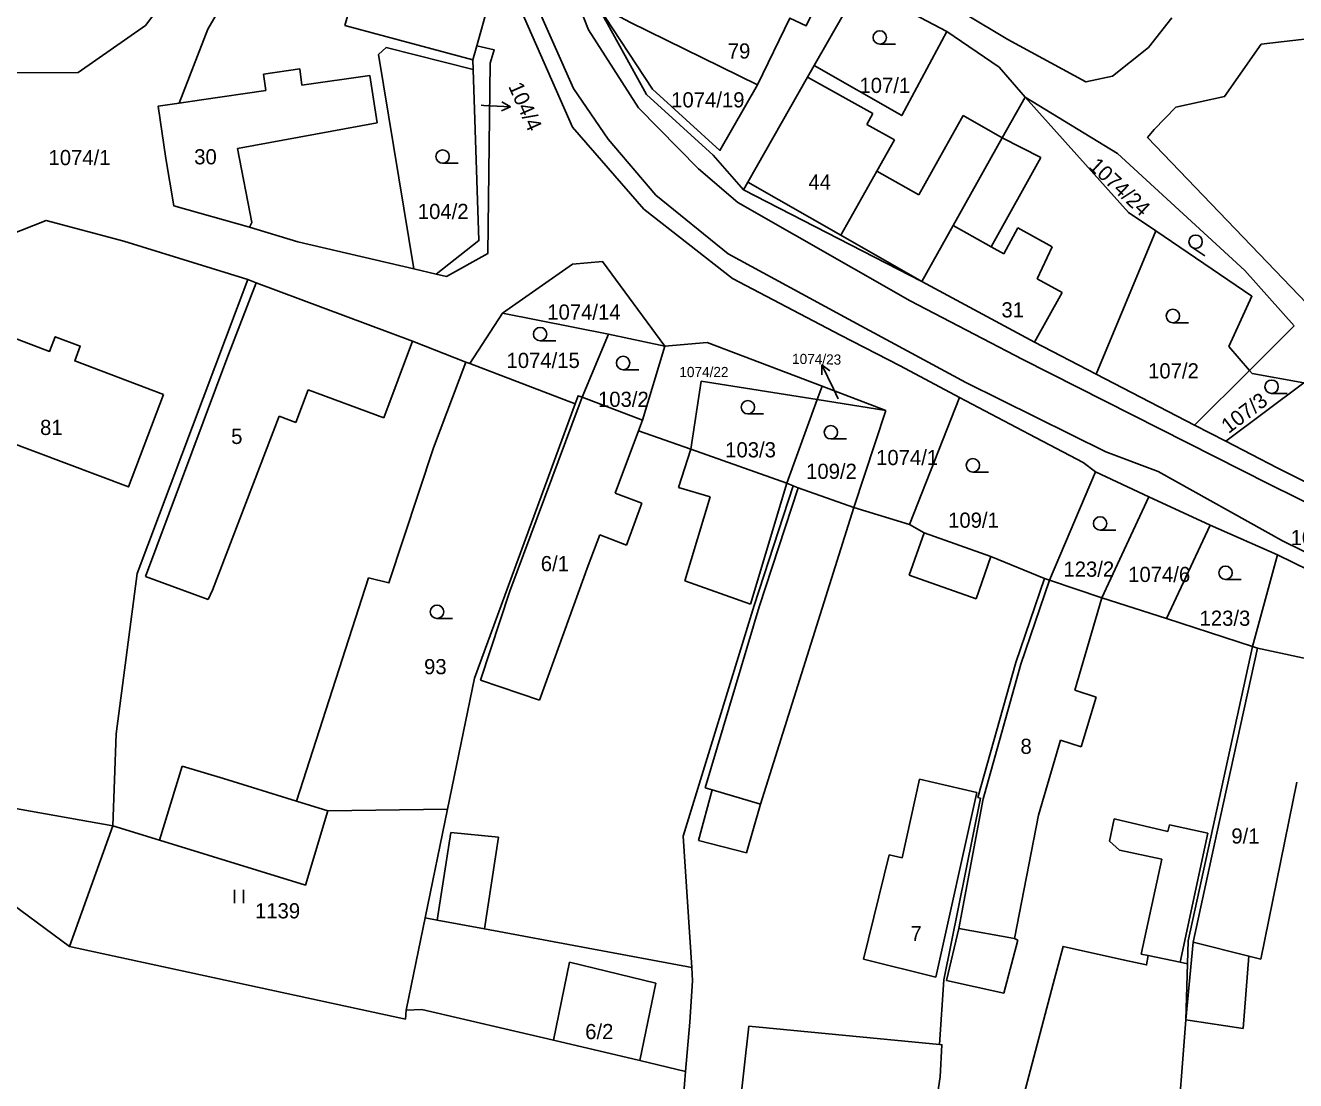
# Model space of a CAD drawing. Extents: x -746176 to -739709, y -1127410 to -1124482.
# Drawn here: x -742376.1 to -742233.7, y -1126206.3 to -1126088.1 of the extents above; entities that cross this region are included whole.
import ezdxf

# ---------------------------------------------------------------- set-up
doc = ezdxf.new("R2010")
doc.units = 0
for name, color, linetype in [('Hranice parcel', 7, 'Continuous'), ('Parcelní čísla', 7, 'Continuous'), ('Pop  PČ popisy', 7, 'Continuous'), ('Vnitřní kresba', 7, 'Continuous'), ('Značky kultur', 7, 'Continuous')]:
    doc.layers.add(name, color=color, linetype=linetype)

msp = doc.modelspace()

# ---------------------------------------------------------------- linework, layer by layer
at = {"layer": 'Hranice parcel'}
for p, q in [((-742325.49, -1126090.34), (-742323.96, -1126084.83)), ((-742325.49, -1126090.34), (-742325.92, -1126091.9)), ((-742325.92, -1126091.9), (-742325.89, -1126092.98)), ((-742263.99, -1126096.11), (-742253.64, -1126102.41)), ((-742275.57, -1126116.75), (-742295.57, -1126106.49)), ((-742256.06, -1126127.14), (-742249.36, -1126111.09)), ((-742332.55, -1126115.34), (-742330.04, -1126115.93)), ((-742326.25, -1126125.97), (-742322.59, -1126120.3)), ((-742322.59, -1126120.3), (-742310.73, -1126122.68)), ((-742233.84, -1126121.75), (-742238.85, -1126126.73)), ((-742310.73, -1126122.68), (-742313.65, -1126129.74)), ((-742304.4, -1126124.01), (-742310.73, -1126122.68)), ((-742306.9, -1126132.3), (-742304.4, -1126124.01)), ((-742238.85, -1126126.73), (-742241.16, -1126124.04)), ((-742326.25, -1126125.97), (-742326.7, -1126125.8)), ((-742314.45, -1126130.46), (-742326.25, -1126125.97)), ((-742300.31, -1126127.94), (-742301.49, -1126135.55)), ((-742287.33, -1126129.99), (-742300.31, -1126127.94)), ((-742256.06, -1126127.14), (-742245.01, -1126132.86)), ((-742245.01, -1126132.86), (-742238.85, -1126126.73)), ((-742238.85, -1126126.73), (-742238.56, -1126127.06)), ((-742287.33, -1126129.99), (-742286.78, -1126128.49)), ((-742286.78, -1126128.49), (-742279.63, -1126131.21)), ((-742313.65, -1126129.74), (-742306.9, -1126132.3)), ((-742290.74, -1126139.38), (-742287.33, -1126129.99)), ((-742279.63, -1126131.21), (-742287.33, -1126129.99)), ((-742271.38, -1126129.77), (-742276.96, -1126144.02)), ((-742283.2, -1126142.1), (-742279.63, -1126131.21)), ((-742241.52, -1126134.66), (-742245.01, -1126132.86)), ((-742301.49, -1126135.55), (-742290.74, -1126139.38)), ((-742290.74, -1126139.38), (-742290.03, -1126139.66)), ((-742261.26, -1126150.24), (-742256.1, -1126138.11)), ((-742256.1, -1126138.11), (-742250.15, -1126140.92)), ((-742276.96, -1126144.02), (-742283.2, -1126142.1)), ((-742255.42, -1126152.21), (-742250.15, -1126140.92)), ((-742250.15, -1126140.92), (-742243.28, -1126144.09)), ((-742243.28, -1126144.09), (-742248.16, -1126154.55)), ((-742243.28, -1126144.09), (-742235.72, -1126147.41)), ((-742238.52, -1126157.67), (-742235.72, -1126147.41)), ((-742235.72, -1126147.41), (-742219.77, -1126155.24)), ((-742261.26, -1126150.24), (-742261.84, -1126150.05)), ((-742255.42, -1126152.21), (-742261.26, -1126150.24)), ((-742248.16, -1126154.55), (-742255.42, -1126152.21)), ((-742238.52, -1126157.67), (-742248.16, -1126154.55)), ((-742408.55, -1126170.19), (-742366.28, -1126177.8)), ((-742342.18, -1126176.09), (-742328.77, -1126175.93)), ((-742328.77, -1126175.93), (-742331.28, -1126188.11)), ((-742366.28, -1126177.8), (-742371.13, -1126191.3)), ((-742331.28, -1126188.11), (-742332.55, -1126194.28)), ((-742332.55, -1126194.28), (-742333.4, -1126198.44)), ((-742302.07, -1126205.33), (-742302.59, -1126211.7))]:
    msp.add_line(p, q, dxfattribs=at)
for points in [[(-742298.44, -1126066.59), (-742298.26, -1126066.59), (-742298.04, -1126066.78), (-742287.48, -1126076.1), (-742286.57, -1126076.81), (-742288.8, -1126083.85), (-742288.85, -1126084.02), (-742287.04, -1126084.92), (-742288.56, -1126088.12), (-742290.4, -1126087.23), (-742294.01, -1126094.72)], [(-742348.85, -1126077.51), (-742351.8, -1126081.83), (-742355.65, -1126088.47), (-742358.86, -1126096.77), (-742361.21, -1126097.12), (-742360.33, -1126102.97), (-742359.44, -1126108.3), (-742350.98, -1126110.66), (-742345.56, -1126112.3), (-742332.55, -1126115.34)], [(-742322.88, -1126080.92), (-742314.75, -1126099.48), (-742306.74, -1126108.67), (-742296.81, -1126116.44), (-742284.71, -1126122.79), (-742278, -1126126.23), (-742271.38, -1126129.77)], [(-742281.13, -1126080.51), (-742265.95, -1126089.64), (-742257.2, -1126094.39), (-742254.21, -1126093.73), (-742250.17, -1126090.53), (-742247.57, -1126087.2)], [(-742287.67, -1126092.56), (-742282.53, -1126083.58), (-742272.79, -1126088.75)], [(-742379.6, -1126093.36), (-742370.19, -1126093.35), (-742362.62, -1126088.05), (-742361.35, -1126086.4)], [(-742312.04, -1126085.73), (-742308.34, -1126087.69), (-742294.01, -1126094.72)], [(-742312.04, -1126085.73), (-742306.45, -1126095.8), (-742299, -1126102.6), (-742295.57, -1126106.49)], [(-742294.01, -1126094.72), (-742298.22, -1126102.06), (-742305.78, -1126095.19), (-742312.04, -1126085.73)], [(-742272.79, -1126088.75), (-742277.83, -1126098.16), (-742287.67, -1126092.56)], [(-742272.79, -1126088.75), (-742266.9, -1126092.74), (-742263.99, -1126096.11)], [(-742226.91, -1126088.92), (-742220.21, -1126088.74), (-742209.67, -1126089.51), (-742205.42, -1126090.21), (-742203.87, -1126091.46), (-742201.62, -1126095.17), (-742208.44, -1126114.62), (-742212.86, -1126123.04), (-742219.9, -1126132.27), (-742250.27, -1126100.63), (-742249.53, -1126099.74), (-742247.13, -1126097.23), (-742241.64, -1126096.04), (-742237.53, -1126090.17), (-742226.91, -1126088.92)], [(-742325.89, -1126092.98), (-742335.63, -1126090.54), (-742336.5, -1126091.32), (-742332.55, -1126115.34)], [(-742330.04, -1126115.93), (-742328.87, -1126116.21), (-742324.26, -1126113.63), (-742323.99, -1126092.3), (-742323.53, -1126090.81), (-742325.49, -1126090.34)], [(-742330.04, -1126115.93), (-742325.25, -1126112.17), (-742325.89, -1126092.98)], [(-742295.57, -1126106.49), (-742295.08, -1126105.63), (-742288.41, -1126093.86), (-742287.67, -1126092.56)], [(-742263.99, -1126096.11), (-742266.59, -1126100.65), (-742272.09, -1126110.5), (-742275.57, -1126116.75)], [(-742249.36, -1126111.09), (-742252.4, -1126109.03), (-742263.99, -1126096.11)], [(-742253.64, -1126102.41), (-742239.39, -1126115.53), (-742233.84, -1126121.75)], [(-742351.14, -1126116.55), (-742365.05, -1126112.26), (-742373.77, -1126109.92), (-742386.77, -1126115.04)], [(-742241.16, -1126124.04), (-742238.58, -1126118.41), (-742249.36, -1126111.09)], [(-742322.59, -1126120.3), (-742314.77, -1126114.82), (-742311.38, -1126114.53), (-742304.4, -1126124.01)], [(-742351.14, -1126116.55), (-742363.54, -1126149.51), (-742365.92, -1126167.47), (-742366.28, -1126177.8)], [(-742326.7, -1126125.8), (-742332.7, -1126123.44), (-742350.2, -1126116.9), (-742351.14, -1126116.55)], [(-742275.57, -1126116.75), (-742262.95, -1126123.57), (-742256.06, -1126127.14)], [(-742360.61, -1126129.44), (-742370.56, -1126125.67), (-742369.93, -1126124), (-742372.74, -1126122.95), (-742373.37, -1126124.6), (-742381.46, -1126121.54), (-742385.41, -1126131.94), (-742364.54, -1126139.8), (-742360.61, -1126129.44)], [(-742304.4, -1126124.01), (-742299.64, -1126123.59), (-742286.78, -1126128.49)], [(-742342.18, -1126176.09), (-742345.69, -1126175.02), (-742337.62, -1126150), (-742335.33, -1126150.55), (-742330.35, -1126135.4), (-742326.7, -1126125.8)], [(-742238.56, -1126127.06), (-742232.76, -1126128.14), (-742241.52, -1126134.66)], [(-742328.77, -1126175.93), (-742325.75, -1126161.24), (-742314.45, -1126130.46)], [(-742314.45, -1126130.46), (-742314.12, -1126129.57), (-742313.65, -1126129.74)], [(-742271.38, -1126129.77), (-742263.55, -1126133.89), (-742257.51, -1126137.07), (-742256.1, -1126138.11)], [(-742301.49, -1126135.55), (-742307.36, -1126133.52), (-742306.9, -1126132.3)], [(-742241.52, -1126134.66), (-742235.74, -1126137.65), (-742212.93, -1126149.05), (-742177.34, -1126171.16)], [(-742290.03, -1126139.66), (-742294.39, -1126153.07), (-742302.36, -1126178.95), (-742301.38, -1126193.67)], [(-742283.2, -1126142.1), (-742289.47, -1126139.88), (-742290.03, -1126139.66)], [(-742261.84, -1126150.05), (-742267.85, -1126147.6), (-742275.32, -1126144.93), (-742276.96, -1126144.02)], [(-742274.79, -1126214.34), (-742273.54, -1126205.94), (-742273.34, -1126202.32), (-742273.6, -1126202.3), (-742273.12, -1126195.05), (-742269.02, -1126174.69), (-742269.3, -1126174.61), (-742265.06, -1126159.49), (-742261.84, -1126150.05)], [(-742245.81, -1126193.24), (-742245.74, -1126190.69), (-742238.52, -1126157.67)], [(-742229.8, -1126159.63), (-742230.81, -1126159.4), (-742237.95, -1126157.86), (-742238.52, -1126157.67)], [(-742366.28, -1126177.8), (-742361.05, -1126179.41), (-742344.7, -1126184.42), (-742342.18, -1126176.09)], [(-742371.13, -1126191.3), (-742382.1, -1126183.23), (-742395.78, -1126181.85), (-742403.65, -1126182.31), (-742424.12, -1126188.09), (-742455.22, -1126201.03)], [(-742331.28, -1126188.11), (-742329.94, -1126188.36), (-742324.62, -1126189.35), (-742301.38, -1126193.67)], [(-742333.4, -1126198.44), (-742333.49, -1126199.45), (-742371.13, -1126191.3)], [(-742275.09, -1126215.95), (-742266.66, -1126217.47), (-742260.87, -1126195.48), (-742259.76, -1126191.3), (-742252.85, -1126192.83), (-742250.39, -1126193.38), (-742250.2, -1126192.33), (-742246.63, -1126193.07), (-742245.81, -1126193.24)], [(-742245.81, -1126193.24), (-742245.98, -1126199.54), (-742247.06, -1126213.57), (-742246.8, -1126213.59)], [(-742301.38, -1126193.67), (-742301.28, -1126195.16), (-742301.61, -1126199.8), (-742302.07, -1126205.33)], [(-742333.4, -1126198.44), (-742331.66, -1126198.39), (-742316.87, -1126201.82), (-742307.21, -1126204.11), (-742302.07, -1126205.33)]]:
    msp.add_lwpolyline(points, dxfattribs=at)
at = {"layer": 'Pop  PČ popisy'}
for p, q in [((-742321.703, -1126097.177), (-742322.677, -1126096.625)), ((-742324.99, -1126097.01), (-742324.7, -1126097.02)), ((-742324.7, -1126097.02), (-742321.703, -1126097.177)), ((-742321.703, -1126097.177), (-742322.729, -1126097.625)), ((-742286.806, -1126126.093), (-742286.817, -1126127.212)), ((-742285.49, -1126128.79), (-742286.806, -1126126.093)), ((-742286.806, -1126126.093), (-742285.916, -1126126.773)), ((-742284.96, -1126129.91), (-742285.49, -1126128.79))]:
    msp.add_line(p, q, dxfattribs=at)
at = {"layer": 'Vnitřní kresba'}
for p, q in [((-742321.12, -1126080.53), (-742314.64, -1126095.13)), ((-742315.8, -1126081.39), (-742312.95, -1126088.54)), ((-742340.28, -1126088.06), (-742339.7, -1126086.09)), ((-742340.28, -1126088.06), (-742325.92, -1126091.9)), ((-742312.95, -1126088.54), (-742307.34, -1126097.28)), ((-742349.39, -1126093.51), (-742345.31, -1126092.91)), ((-742349.39, -1126093.51), (-742349.14, -1126095.36)), ((-742345.31, -1126092.91), (-742345.1, -1126094.77)), ((-742345.1, -1126094.77), (-742337.49, -1126093.66)), ((-742337.49, -1126093.66), (-742336.66, -1126098.98)), ((-742288.41, -1126093.86), (-742281.08, -1126097.94)), ((-742314.64, -1126095.13), (-742310.74, -1126100.8)), ((-742358.86, -1126096.77), (-742356.35, -1126096.41)), ((-742356.35, -1126096.41), (-742349.14, -1126095.36)), ((-742307.34, -1126097.28), (-742300.63, -1126104.14)), ((-742281.75, -1126099.15), (-742281.08, -1126097.94)), ((-742275.93, -1126107.04), (-742270.96, -1126098.15)), ((-742270.96, -1126098.15), (-742266.59, -1126100.65)), ((-742352.31, -1126101.84), (-742336.66, -1126098.98)), ((-742281.75, -1126099.15), (-742278.67, -1126100.89)), ((-742310.74, -1126100.8), (-742305.42, -1126107.1)), ((-742280.64, -1126104.39), (-742278.67, -1126100.89)), ((-742266.59, -1126100.65), (-742262.26, -1126102.86)), ((-742352.31, -1126101.84), (-742350.71, -1126110.14)), ((-742267.61, -1126112.55), (-742262.26, -1126102.86)), ((-742300.63, -1126104.14), (-742296.2, -1126107.89)), ((-742284.68, -1126111.56), (-742280.64, -1126104.39)), ((-742280.64, -1126104.39), (-742275.93, -1126107.04)), ((-742295.08, -1126105.63), (-742284.68, -1126111.56)), ((-742305.42, -1126107.1), (-742297.3, -1126113.67)), ((-742296.2, -1126107.89), (-742276.88, -1126118.92)), ((-742350.98, -1126110.66), (-742350.71, -1126110.14)), ((-742272.09, -1126110.5), (-742267.8, -1126112.88)), ((-742266.4, -1126113.66), (-742264.83, -1126110.75)), ((-742264.83, -1126110.75), (-742260.96, -1126112.88)), ((-742284.68, -1126111.56), (-742275.57, -1126116.75)), ((-742297.3, -1126113.67), (-742283.82, -1126120.97)), ((-742267.8, -1126112.88), (-742267.61, -1126112.55)), ((-742267.8, -1126112.88), (-742266.4, -1126113.66)), ((-742262.66, -1126116.47), (-742260.96, -1126112.88)), ((-742262.66, -1126116.47), (-742259.87, -1126118.01)), ((-742353.49, -1126125.42), (-742350.2, -1126116.9)), ((-742262.95, -1126123.57), (-742259.87, -1126118.01)), ((-742276.88, -1126118.92), (-742264.25, -1126125.49)), ((-742283.82, -1126120.97), (-742270.64, -1126128.09)), ((-742335.92, -1126132.03), (-742332.7, -1126123.44)), ((-742362.62, -1126149.84), (-742353.49, -1126125.42)), ((-742264.25, -1126125.49), (-742236.63, -1126139.49)), ((-742345.76, -1126132.56), (-742344.4, -1126128.89)), ((-742344.4, -1126128.89), (-742335.92, -1126132.03)), ((-742270.64, -1126128.09), (-742254.96, -1126135.85)), ((-742321.76, -1126151.49), (-742313.99, -1126130.63)), ((-742313.99, -1126130.63), (-742313.65, -1126129.74)), ((-742355.11, -1126151.35), (-742347.65, -1126131.87)), ((-742347.65, -1126131.87), (-742345.76, -1126132.56)), ((-742309.98, -1126140.49), (-742307.36, -1126133.52)), ((-742302.87, -1126139.86), (-742301.49, -1126135.55)), ((-742254.96, -1126135.85), (-742249.1, -1126138.06)), ((-742294.78, -1126152.93), (-742290.74, -1126139.38)), ((-742249.1, -1126138.06), (-742235.14, -1126145.83)), ((-742309.98, -1126140.49), (-742306.99, -1126141.62)), ((-742302.87, -1126139.86), (-742299.31, -1126140.9)), ((-742293.82, -1126153.25), (-742289.47, -1126139.88)), ((-742236.63, -1126139.49), (-742214.05, -1126150.74)), ((-742308.71, -1126146.33), (-742306.99, -1126141.62)), ((-742302.15, -1126150.33), (-742299.31, -1126140.9)), ((-742293.68, -1126175.34), (-742283.2, -1126142.1)), ((-742277.02, -1126149.7), (-742275.32, -1126144.93)), ((-742312.98, -1126148.6), (-742311.68, -1126145.17)), ((-742311.68, -1126145.17), (-742308.71, -1126146.33)), ((-742235.14, -1126145.83), (-742216.99, -1126154.85)), ((-742269.51, -1126152.34), (-742267.85, -1126147.6)), ((-742318.44, -1126163.68), (-742312.98, -1126148.6)), ((-742362.62, -1126149.84), (-742355.61, -1126152.4)), ((-742302.15, -1126150.33), (-742294.78, -1126152.93)), ((-742277.02, -1126149.7), (-742269.51, -1126152.34)), ((-742264.5, -1126159.68), (-742261.26, -1126150.24)), ((-742355.61, -1126152.4), (-742355.11, -1126151.35)), ((-742325.07, -1126161.47), (-742321.76, -1126151.49)), ((-742258.44, -1126162.59), (-742255.42, -1126152.21)), ((-742299.86, -1126173.52), (-742293.82, -1126153.25)), ((-742242.53, -1126178.6), (-742237.95, -1126157.86)), ((-742268.58, -1126174.24), (-742264.5, -1126159.68)), ((-742325.07, -1126161.47), (-742318.44, -1126163.68)), ((-742258.44, -1126162.59), (-742256.05, -1126163.36)), ((-742257.72, -1126168.93), (-742256.05, -1126163.36)), ((-742262.5, -1126176.58), (-742260.05, -1126168.17)), ((-742260.05, -1126168.17), (-742257.72, -1126168.93)), ((-742361.05, -1126179.41), (-742358.51, -1126171.1)), ((-742358.51, -1126171.1), (-742353.86, -1126172.49)), ((-742353.86, -1126172.49), (-742345.69, -1126175.02)), ((-742299.86, -1126173.52), (-742299.11, -1126173.74)), ((-742277.79, -1126181.37), (-742275.84, -1126172.55)), ((-742275.84, -1126172.55), (-742269.42, -1126174.05)), ((-742237.59, -1126192.75), (-742233.53, -1126172.88)), ((-742300.61, -1126179.42), (-742299.11, -1126173.74)), ((-742299.11, -1126173.74), (-742293.68, -1126175.34)), ((-742274.02, -1126194.74), (-742269.42, -1126174.05)), ((-742271.45, -1126189.28), (-742268.73, -1126174.77)), ((-742268.73, -1126174.77), (-742268.58, -1126174.24)), ((-742295.23, -1126180.82), (-742293.68, -1126175.34)), ((-742265.2, -1126190.4), (-742262.5, -1126176.58)), ((-742254.53, -1126179.5), (-742254.01, -1126176.99)), ((-742254.01, -1126176.99), (-742248, -1126178.41)), ((-742248, -1126178.41), (-742247.84, -1126177.67)), ((-742247.84, -1126177.67), (-742243.51, -1126178.62)), ((-742329.94, -1126188.36), (-742328.41, -1126178.52)), ((-742328.41, -1126178.52), (-742323.05, -1126179.05)), ((-742324.62, -1126189.35), (-742323.05, -1126179.05)), ((-742246.63, -1126193.07), (-742243.51, -1126178.62)), ((-742245.16, -1126190.83), (-742242.53, -1126178.6)), ((-742300.61, -1126179.42), (-742295.23, -1126180.82)), ((-742254.53, -1126179.5), (-742253.42, -1126180.51)), ((-742253.42, -1126180.51), (-742248.68, -1126181.54)), ((-742282.11, -1126192.72), (-742279.25, -1126181.03)), ((-742279.25, -1126181.03), (-742277.79, -1126181.37)), ((-742250.98, -1126192.17), (-742248.68, -1126181.54)), ((-742272.83, -1126195.11), (-742271.45, -1126189.28)), ((-742271.45, -1126189.28), (-742265.2, -1126190.4)), ((-742266.38, -1126196.53), (-742264.83, -1126190.6)), ((-742265.2, -1126190.4), (-742264.83, -1126190.6)), ((-742245.98, -1126199.54), (-742245.16, -1126190.83)), ((-742245.16, -1126190.83), (-742238.94, -1126192.41)), ((-742316.87, -1126201.82), (-742315.09, -1126193.06)), ((-742315.09, -1126193.06), (-742305.41, -1126195.41)), ((-742282.11, -1126192.72), (-742274.02, -1126194.74)), ((-742250.98, -1126192.17), (-742250.2, -1126192.33)), ((-742239.56, -1126200.52), (-742238.94, -1126192.41)), ((-742238.94, -1126192.41), (-742237.59, -1126192.75)), ((-742307.21, -1126204.11), (-742305.41, -1126195.41)), ((-742272.83, -1126195.11), (-742266.38, -1126196.53)), ((-742296.36, -1126212.29), (-742294.97, -1126200.25)), ((-742294.97, -1126200.25), (-742273.6, -1126202.3)), ((-742245.98, -1126199.54), (-742245.51, -1126199.61)), ((-742245.51, -1126199.61), (-742239.56, -1126200.52))]:
    msp.add_line(p, q, dxfattribs=at)
at = {"layer": 'Značky kultur'}
for p, q in [((-742280.303, -1126090.15), (-742278.553, -1126090.15)), ((-742329.313, -1126103.51), (-742327.563, -1126103.51)), ((-742245.314, -1126112.924), (-742243.863, -1126113.903)), ((-742247.443, -1126121.38), (-742245.693, -1126121.38)), ((-742318.383, -1126123.41), (-742316.633, -1126123.41)), ((-742309.073, -1126126.65), (-742307.323, -1126126.65)), ((-742236.373, -1126129.31), (-742234.623, -1126129.31)), ((-742295.093, -1126131.61), (-742293.343, -1126131.61)), ((-742285.783, -1126134.42), (-742284.033, -1126134.42)), ((-742269.863, -1126138.12), (-742268.113, -1126138.12)), ((-742255.603, -1126144.64), (-742253.853, -1126144.64)), ((-742241.543, -1126150.17), (-742239.793, -1126150.17)), ((-742329.943, -1126154.54), (-742328.193, -1126154.54)), ((-742352.651, -1126186.46), (-742352.651, -1126184.96)), ((-742351.65, -1126186.46), (-742351.65, -1126184.96))]:
    msp.add_line(p, q, dxfattribs=at)
for centre in [(-742280.303, -1126089.4), (-742329.313, -1126102.76), (-742244.895, -1126112.302), (-742247.443, -1126120.63), (-742318.383, -1126122.66), (-742309.073, -1126125.9), (-742236.373, -1126128.56), (-742295.093, -1126130.86), (-742285.783, -1126133.67), (-742269.863, -1126137.37), (-742255.603, -1126143.89), (-742241.543, -1126149.42), (-742329.943, -1126153.79)]:
    msp.add_circle(centre, 0.75, dxfattribs=at)

# ---------------------------------------------------------------- texts
at = {"layer": 'Parcelní čísla'}
for s, height, p in [('79', 1.7, (-742297.342, -1126091.77)), ('107/1', 1.7, (-742282.583, -1126095.63)), ('1074/19', 1.7, (-742303.688, -1126097.25)), ('1074/1', 1.7, (-742373.495, -1126103.72)), ('30', 1.7, (-742357.162, -1126103.63)), ('44', 1.7, (-742288.302, -1126106.46)), ('104/2', 1.7, (-742332.093, -1126109.76)), ('1074/14', 1.7, (-742317.58, -1126121.04)), ('31', 1.7, (-742266.662, -1126120.79)), ('1074/15', 1.7, (-742322.15, -1126126.46)), ('1074/22', 1.139, (-742302.771, -1126127.479)), ('107/2', 1.7, (-742250.223, -1126127.63)), ('103/2', 1.7, (-742311.893, -1126130.82)), ('81', 1.7, (-742374.442, -1126133.97)), ('5', 1.7, (-742353.02, -1126134.98)), ('103/3', 1.7, (-742297.633, -1126136.48)), ('1074/1', 1.7, (-742280.715, -1126137.35)), ('109/2', 1.7, (-742288.563, -1126138.89)), ('109/1', 1.7, (-742272.643, -1126144.37)), ('1080/8', 1.7, (-742234.24, -1126146.32)), ('6/1', 1.7, (-742318.308, -1126149.24)), ('123/2', 1.7, (-742259.713, -1126149.86)), ('1074/6', 1.7, (-742252.455, -1126150.45)), ('123/3', 1.7, (-742244.453, -1126155.36)), ('93', 1.7, (-742331.392, -1126160.79)), ('8', 1.7, (-742264.53, -1126169.72)), ('9/1', 1.7, (-742240.888, -1126179.77)), ('1139', 1.7, (-742350.347, -1126188.16)), ('7', 1.7, (-742276.85, -1126190.71)), ('6/2', 1.7, (-742313.328, -1126201.7))]:
    msp.add_text(s, height=height, dxfattribs=at).set_placement(p)
for s, height, rotation, p in [('104/4', 1.7, 294, (-742321.982, -1126094.878)), ('1074/24', 1.7, 317, (-742256.986, -1126103.964)), ('1074/23', 1.139, 359, (-742290.141, -1126125.994)), ('107/3', 1.7, 37, (-742241.203, -1126133.877))]:
    msp.add_text(s, height=height, rotation=rotation, dxfattribs=at).set_placement(p)

doc.saveas('drawing.dxf')
